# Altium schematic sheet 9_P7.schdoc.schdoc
size 309 x 223 mm; Symbol: A4_Schematic_0605; Device: A4_Schematic_0605; @Project Name: MDIO-Board_Rev_01(0124); @Page Count: 10; @Update Date: 2024-05-24; @Create Date: 2024-05-19; @Schematic Name: Schematic1; @Page No: 7; @Page Name: P7
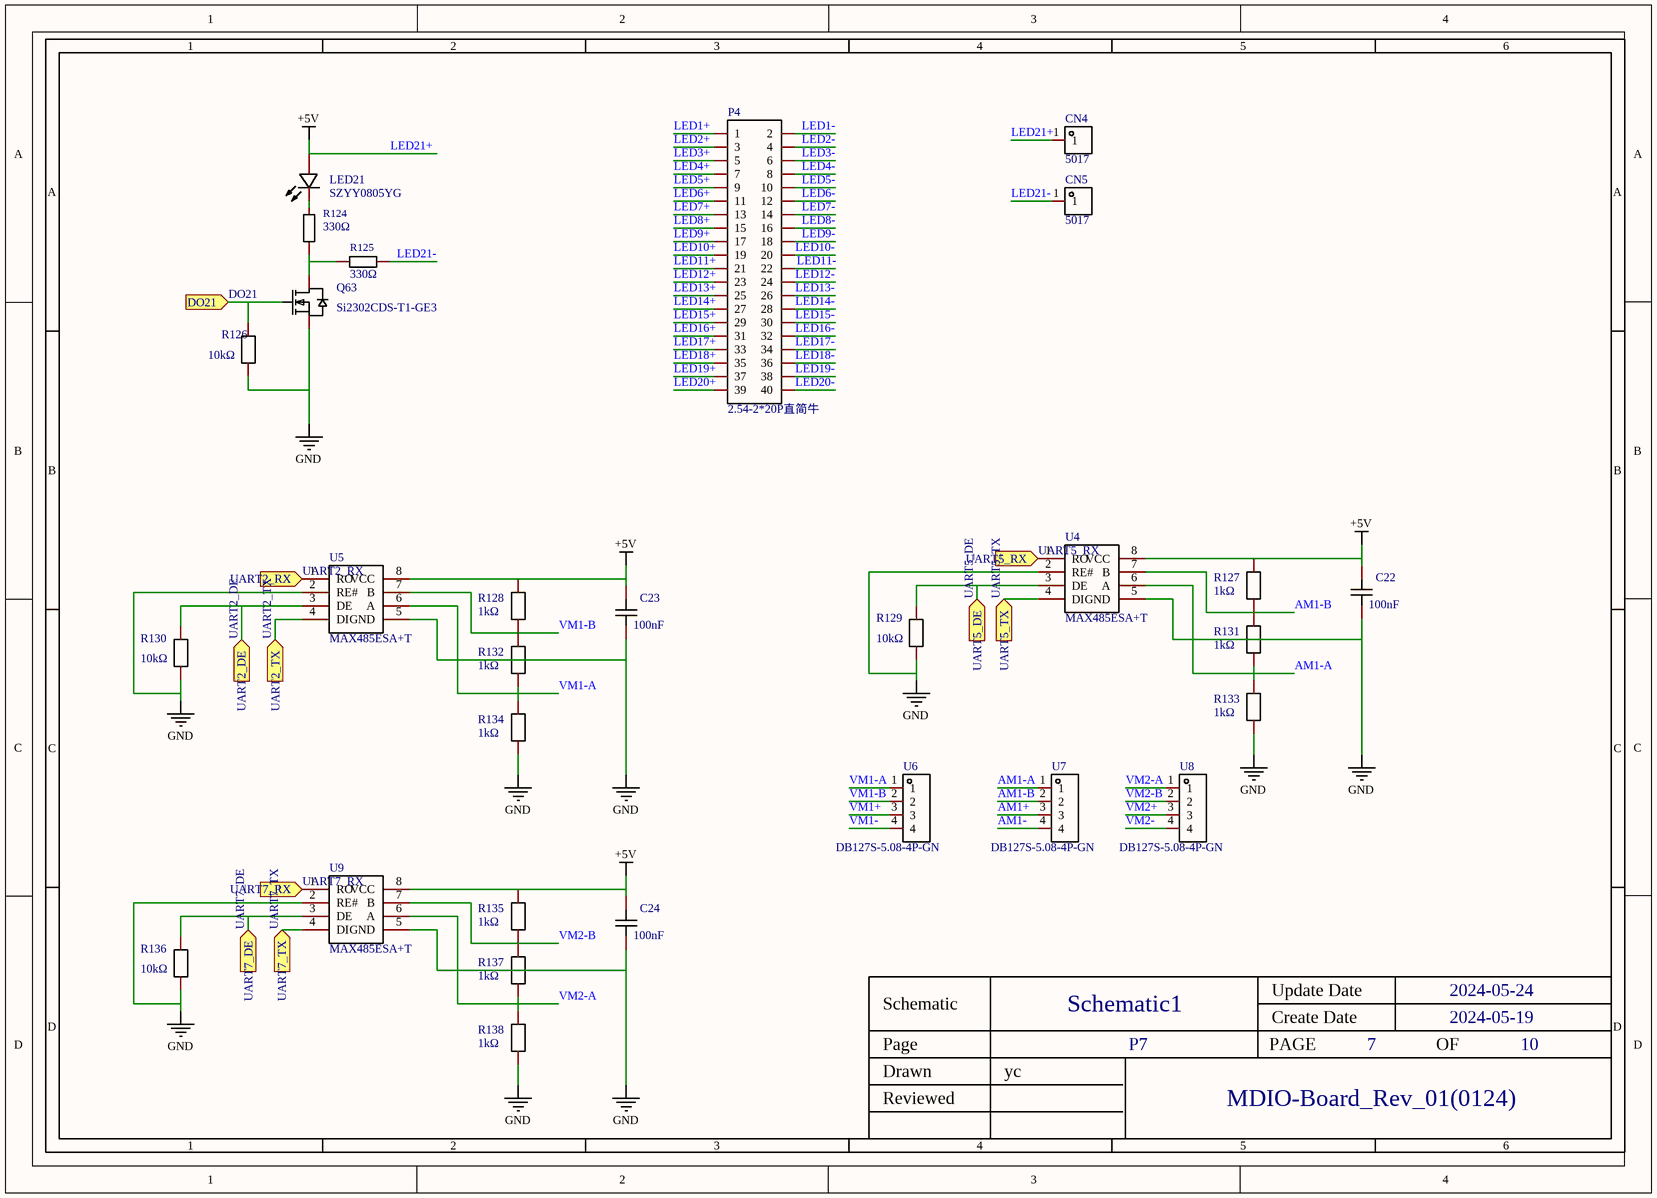
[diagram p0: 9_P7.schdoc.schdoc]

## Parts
C22  100nF  [C0603]
C23  100nF  [C0603]
C24  100nF  [C0603]
CN4  5017  [CONN-SMD_5017]
CN5  5017  [CONN-SMD_5017]
LED21  SZYY0805YG  [LED0805-R-RD_GREEN]
P4  2.54-2*20P直简牛  [IDC-TH_40P-P2.54_C9138]
Q63  Si2302CDS-T1-GE3  [SOT-23_L2.9-W1.3-P1.90-LS2.4-BR]
R124  330Ω  [R0603]
R125  330Ω  [R0603]
R126  10kΩ  [R0603]
R127  1kΩ  [R0603]
R128  1kΩ  [R0603]
R129  10kΩ  [R0603]
R130  10kΩ  [R0603]
R131  1kΩ  [R0603]
R132  1kΩ  [R0603]
R133  1kΩ  [R0603]
R134  1kΩ  [R0603]
R135  1kΩ  [R0603]
R136  10kΩ  [R0603]
R137  1kΩ  [R0603]
R138  1kΩ  [R0603]
U4  MAX485ESA+T  [SOIC-8_L5.0-W4.0-P1.27-LS6.0-BL]
U5  MAX485ESA+T  [SOIC-8_L5.0-W4.0-P1.27-LS6.0-BL]
U6  DB127S-5.08-4P-GN  [CONN-TH_4P-P5.08_DB127S-5.08-4P-GN]
U7  DB127S-5.08-4P-GN  [CONN-TH_4P-P5.08_DB127S-5.08-4P-GN]
U8  DB127S-5.08-4P-GN  [CONN-TH_4P-P5.08_DB127S-5.08-4P-GN]
U9  MAX485ESA+T  [SOIC-8_L5.0-W4.0-P1.27-LS6.0-BL]

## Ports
DO21 (in), UART2_DE (in), UART2_RX (in), UART2_TX (in), UART5_DE (in), UART5_RX (in), UART5_TX (in), UART7_DE (in), UART7_RX (in), UART7_TX (in)

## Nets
GND: C22.2 C23.2 C24.2 Q63.2(S) R126.1 R129.1 R130.1 R133.1 R134.1 R136.1 R138.1 U4.2(RE#) U4.5(GND) U5.2(RE#) U5.5(GND) U9.2(RE#) U9.5(GND)
LED21+: C22.1 C23.1 C24.1 CN4.1 LED21.1(+) R127.2 R128.2 R135.2 U4.8(VCC) U5.8(VCC) U9.8(VCC)  [also labelled +5V]
AM1+: U7.3
AM1-: U7.4
AM1-A: R131.1 R133.2 U4.6(A) U7.1
AM1-B: R127.1 R131.2 U4.7(B) U7.2
DO21: Q63.1(G) R126.2 ; port DO21
LED1+: P4.1
LED1-: P4.2
LED2+: P4.3
LED2-: P4.4
LED3+: P4.5
LED3-: P4.6
LED4+: P4.7
LED4-: P4.8
LED5+: P4.9
LED5-: P4.10
LED6+: P4.11
LED6-: P4.12
LED7+: P4.13
LED7-: P4.14
LED8+: P4.15
LED8-: P4.16
LED9+: P4.17
LED9-: P4.18
LED10+: P4.19
LED10-: P4.20
LED11+: P4.21
LED11-: P4.22
LED12+: P4.23
LED12-: P4.24
LED13+: P4.25
LED13-: P4.26
LED14+: P4.27
LED14-: P4.28
LED15+: P4.29
LED15-: P4.30
LED16+: P4.31
LED16-: P4.32
LED17+: P4.33
LED17-: P4.34
LED18+: P4.35
LED18-: P4.36
LED19+: P4.37
LED19-: P4.38
LED20+: P4.39
LED20-: P4.40
LED21-: CN5.1 R125.1
UART2_DE: R130.2 U5.3(DE) ; port UART2_DE
UART2_RX: U5.1(RO) ; port UART2_RX
UART2_TX: U5.4(DI) ; port UART2_TX
UART5_DE: R129.2 U4.3(DE) ; port UART5_DE
UART5_RX: U4.1(RO) ; port UART5_RX
UART5_TX: U4.4(DI) ; port UART5_TX
UART7_DE: R136.2 U9.3(DE) ; port UART7_DE
UART7_RX: U9.1(RO) ; port UART7_RX
UART7_TX: U9.4(DI) ; port UART7_TX
VM1+: U6.3
VM1-: U6.4
VM1-A: R132.1 R134.2 U5.6(A) U6.1
VM1-B: R128.1 R132.2 U5.7(B) U6.2
VM2+: U8.3
VM2-: U8.4
VM2-A: R137.1 R138.2 U8.1 U9.6(A)
VM2-B: R135.1 R137.2 U8.2 U9.7(B)
NetLED21_2: LED21.2(-) R124.2
NetQ63_3: Q63.3(D) R124.1 R125.2

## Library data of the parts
C22-C24 = CC0603KRX7R9BB104: Manufacturer: YAGEO(国巨); Add into BOM: yes; Tolerance: ±10%; Description: Capacitance: Tolerance:±10% Tolerance:±10% Voltage Rated: Temperature Coefficient:
CN4 CN5 = 5017: Symbol: 5017_C9900015874; Add into BOM: yes
LED21 = SZYY0805YG: Manufacturer: yongyu(永裕光电); Add into BOM: yes; Emitted Color: Green-yellow; Description: Emitted Color:Green-yellow
P4 = 2.54-2*20P直简牛: Manufacturer: BOOMELE(博穆精密); Symbol: HDR-IDC-2.54-2X20P; Add into BOM: yes; Connector Type: 简牛座; Pitch: 2.54mm; Structure: 2x20P; Holder Type: Straight; Pin Number in each Row: 20; Description: Connector Type:简牛座 Pitch:2.54mm Structure:2x20P Holder Type:Straight Row Spacing:2.54mm Number of Rows:2 Pin Number in each Row:20 Contact Material:- Contact Plating:-
Q63 = Si2302CDS-T1-GE3: Manufacturer: VISHAY(威世); Add into BOM: yes; Type: 1个NChannel; Drain Source On Resistance (RDS(on)@Vgs,Id): 57mΩ@4.5V,3.6A; Gate Threshold Voltage (Vgs(th)@Id): 850mV@250uA; Total Gate Charge (Qg@Vgs): 5.5nC@4.5V; Description: Type:1个NChannel Drain Source Voltage (Vdss): Continuous Drain Current (Id): Power Dissipation (Pd): Drain Source On Resistance (RDS(on)@Vgs,Id):57mΩ@4.5V,3.6A Gate Threshold Voltage (Vgs(th)@Id):850mV@250uA Total Gate Charge (Qg@Vgs):5.5nC@4.5V Operating
R124 R125 = 0603WAF3300T5E: Manufacturer: UNI-ROYAL(厚声); Add into BOM: yes; Tolerance: ±1%; Temperature Coefficient: ±100ppm/℃; Description: Type:Thick Film Resistors Resistance: Tolerance:±1% Tolerance:±1% Power(Watts): Overload Voltage (Max): Temperature Coefficient:±100ppm/℃ Temperature Coefficient:±100ppm/℃ Operating Temperature Range:-55℃~+155℃ Operating Temperature Range:-55℃~+155℃
R126-R138 = SCR0603J10K: Manufacturer: VO(翔胜); Add into BOM: yes; Tolerance: ±5%; Description: Type:Thick Film Resistors Resistance: Tolerance:±5% Tolerance:±5% Power(Watts): Overload Voltage (Max): Operating Temperature Range:-55℃~+155℃ Operating Temperature Range:-55℃~+155℃
U4 U5 U9 = MAX485ESA+T: Manufacturer: ADI(亚德诺)/MAXIM(美信); Add into BOM: yes; Types: transceiver; Supply Voltage: 4.75V~5.25V; Data Rate: 2.5Mbps; Driver/receiver: 1/1; Description: Types:transceiver Supply Voltage:4.75V~5.25V Supply Voltage:4.75V~5.25V Data Rate:2.5Mbps Data Rate:2.5Mbps Driver/receiver:1/1 Operating Temperature:-40℃~+85℃ Operating Temperature:-40℃~+85℃
U6-U8 = DB127S-5.08-4P-GN: Manufacturer: DORABO(地博电气); Add into BOM: yes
